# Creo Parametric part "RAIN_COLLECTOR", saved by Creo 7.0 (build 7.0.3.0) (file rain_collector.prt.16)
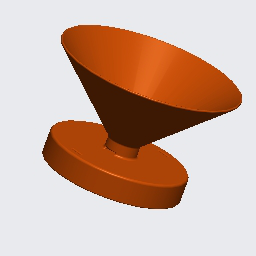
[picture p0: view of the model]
Units: millimeter Kilogram Sec (mmKs); MM, KILOGRAM, SECS

Created from: XX_SOLID_PART_MMKS_ABS.PRT

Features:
  1. coordinate system
  2. datum plane "RIGHT"
  3. datum plane "TOP"
  4. datum plane "FRONT"
  5. extrusion "Extrude 1"
  6. extruded cut "Extrude 2"
  7. cut
  8. extrusion "Extrude 4"
  9. extruded cut "Extrude 5"
  10. extrusion "Extrude 6"
  11. extruded cut "Extrude 7"
  12. revolve "Revolve 1"
  13. chamfer "Chamfer 1"
  14. round "Round 1"
  15. round "Round 2"
  16. round "Round 3"
  17. round "Round 4"
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
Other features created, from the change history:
  round "Round 5"
  chamfer "Chamfer 2" (2 times)
  round "Round 6" (3 times)
  round "Round 7"
  round "Round 8"
  round "Round 9"
  round "Round 10"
